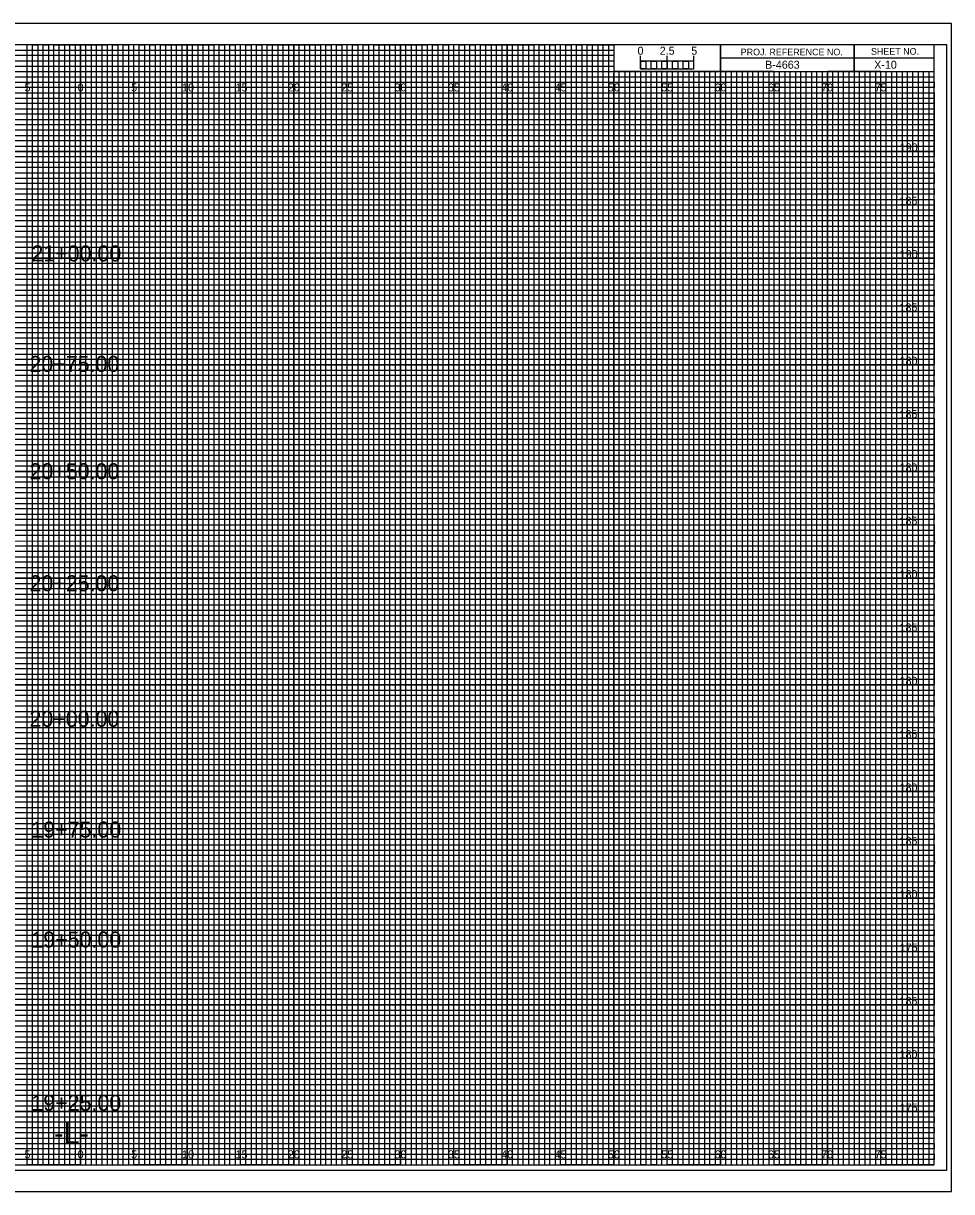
# Model space of a CAD drawing. Extents: x -7 to 162, y 878 to 987.
# Drawn here: x 74.6 to 161.7, y 877.5 to 987 of the extents above; entities that cross this region are included whole.
import ezdxf

# ---------------------------------------------------------------- set-up
doc = ezdxf.new("R2010")
doc.units = 0
for name, color, linetype in [('Prop XS Alignment Label', 7, 'Continuous'), ('Prop XS Bar Scale Labels', 7, 'Continuous'), ('Prop XS Elevation Labels', 7, 'Continuous'), ('Prop XS Offset Labels', 7, 'Continuous'), ('Prop XS Project Number', 7, 'Continuous'), ('Prop XS Sheet Number', 7, 'Continuous'), ('Prop XS Station Labels', 7, 'Continuous'), ('Sheet Cross Section CELL', 7, 'Continuous'), ('Sheet Cross Section Grid Major CELL', 7, 'Continuous'), ('Sheet Cross Section Grid Middle CELL', 7, 'Continuous'), ('Sheet Cross Section Grid Minor 1 CELL', 7, 'Continuous'), ('Sheet Cross Section Grid Minor 2 CELL', 7, 'Continuous'), ('Sheet Cross Section Scale CELL', 7, 'Continuous'), ('Sheet Cutting Line CELL', 7, 'Continuous'), ('Sheet DOT Grid CELL', 7, 'Continuous'), ('Sheet Plot Border Inside CELL', 7, 'Continuous'), ('Sheet Plot Border Outside CELL', 7, 'Continuous')]:
    doc.layers.add(name, color=color, linetype=linetype)

msp = doc.modelspace()

# ---------------------------------------------------------------- linework, layer by layer
at = {"layer": 'Sheet Cross Section CELL'}
for p, q in [((152.5, 985), (152.5, 982.5)), ((152.5, 982.5), (152.5, 985)), ((160, 983.75), (140, 983.75)), ((140, 983.75), (140, 982.5)), ((140, 982.5), (160, 982.5))]:
    msp.add_line(p, q, dxfattribs=at)
for points in [[(160, 985), (0, 985), (0, 880), (160, 880)], [(140, 985), (130, 985), (130, 982.51), (140, 982.51)], [(160, 985), (140, 985), (140, 982.5), (160, 982.5)]]:
    msp.add_lwpolyline(points, close=True, dxfattribs=at)
at = {"layer": 'Sheet Cross Section Grid Major CELL'}
for p, q in [((75, 985), (70, 985)), ((75, 880), (75, 985)), ((85, 985), (80, 985)), ((80, 985), (80, 880)), ((85, 880), (85, 985)), ((95, 985), (90, 985)), ((90, 985), (90, 880)), ((95, 880), (95, 985)), ((105, 985), (100, 985)), ((100, 985), (100, 880)), ((105, 880), (105, 985)), ((115, 985), (110, 985)), ((110, 985), (110, 880)), ((115, 880), (115, 985)), ((125, 985), (120, 985)), ((120, 985), (120, 880)), ((125, 880), (125, 985)), ((130, 985), (130, 880)), ((135, 880), (135, 982.5)), ((145, 982.5), (140, 982.5)), ((140, 982.5), (140, 880)), ((145, 880), (145, 982.5)), ((155, 982.5), (150, 982.5)), ((150, 982.5), (150, 880)), ((155, 880), (155, 982.5)), ((80, 880), (75, 880)), ((90, 880), (85, 880)), ((100, 880), (95, 880)), ((110, 880), (105, 880)), ((120, 880), (115, 880)), ((130, 880), (125, 880)), ((140, 880), (135, 880)), ((150, 880), (145, 880)), ((160, 880), (155, 880)), ((160, 880), (160, 880))]:
    msp.add_line(p, q, dxfattribs=at)
for points in [[(0, 980), (160, 980), (160, 975), (0, 975)], [(0, 970), (160, 970), (160, 965), (0, 965)], [(0, 960), (160, 960), (160, 955), (0, 955)], [(0, 950), (160, 950), (160, 945), (0, 945)], [(0, 940), (160, 940), (160, 935), (0, 935)], [(0, 930), (160, 930), (160, 925), (0, 925)], [(0, 920), (160, 920), (160, 915), (0, 915)], [(0, 910), (160, 910), (160, 905), (0, 905)], [(0, 900), (160, 900), (160, 895), (0, 895)], [(0, 890), (160, 890), (160, 885), (0, 885)]]:
    msp.add_lwpolyline(points, dxfattribs=at)
at = {"layer": 'Sheet Cross Section Grid Middle CELL'}
for points in [[(72.5, 880), (77.5, 880), (77.5, 985), (82.5, 985), (82.5, 880), (87.5, 880), (87.5, 985), (92.5, 985), (92.5, 880), (97.5, 880), (97.5, 985), (102.5, 985), (102.5, 880), (107.5, 880), (107.5, 985), (112.5, 985), (112.5, 880), (117.5, 880), (117.5, 985), (122.5, 985), (122.5, 880), (127.5, 880), (127.5, 985), (129.97, 985), (130, 985), (130, 982.5), (132.5, 982.5), (132.5, 880), (137.5, 880), (137.5, 982.5), (142.5, 982.5), (142.5, 880), (147.5, 880), (147.5, 982.5), (152.5, 982.5), (152.5, 880), (157.5, 880), (157.5, 982.5)], [(0, 982.5), (137.5, 982.5)], [(0, 972.5), (160, 972.5), (160, 977.5), (0, 977.5)], [(0, 962.5), (160, 962.5), (160, 967.5), (0, 967.5)], [(0, 952.5), (160, 952.5), (160, 957.5), (0, 957.5)], [(0, 942.5), (160, 942.5), (160, 947.5), (0, 947.5)], [(0, 932.5), (160, 932.5), (160, 937.5), (0, 937.5)], [(0, 922.5), (160, 922.5), (160, 927.5), (0, 927.5)], [(0, 912.5), (160, 912.5), (160, 917.5), (0, 917.5)], [(0, 902.5), (160, 902.5), (160, 907.5), (0, 907.5)], [(0, 892.5), (160, 892.5), (160, 897.5), (0, 897.5)], [(0, 882.5), (160, 882.5), (160, 887.5), (0, 887.5)]]:
    msp.add_lwpolyline(points, dxfattribs=at)
at = {"layer": 'Sheet Cross Section Grid Minor 1 CELL'}
for p, q in [((0, 984.5), (130, 984.5)), ((130, 984.5), (130, 983.99)), ((130, 983.99), (0, 983.99)), ((0, 983.5), (130, 983.5)), ((130, 983.5), (130, 982.95)), ((130, 982.95), (0, 982.95)), ((0, 982), (160, 982))]:
    msp.add_line(p, q, dxfattribs=at)
for points in [[(0, 981.5), (135, 981.5), (160, 981.5), (160, 981), (0, 981)], [(0, 980.5), (160, 980.5), (160, 979.5), (0, 979.5)], [(0, 979), (160, 979), (160, 978.5), (0, 978.49)], [(0, 978), (160, 978), (160, 977), (0, 977)], [(0, 976.5), (160, 976.5), (160, 976), (0, 976)], [(0, 975.5), (160, 975.5), (160, 974.5), (0, 974.5)], [(0, 974), (160, 974), (160, 973.5), (0, 973.5)], [(0, 973), (160, 973), (160, 972), (0, 972)], [(0, 971.5), (160, 971.5), (160, 971), (0, 971)], [(0, 970.5), (160, 970.5), (160, 969.5), (0, 969.5)], [(0, 969), (160, 969), (160, 968.5), (0, 968.5)], [(0, 968), (160, 968), (160, 966.98), (160, 966.5), (160, 966), (0, 966)], [(0, 967), (160, 967), (160, 966.5), (0, 966.5)], [(0, 965.5), (160, 965.5), (160, 964.5), (0, 964.51)], [(0, 964.51), (160, 964.5), (160, 964), (0, 964)], [(0, 963.5), (160, 963.5), (160, 963), (0, 963)], [(0, 962), (160, 962), (160, 961.5), (0, 961.5)], [(0, 961), (160, 961), (160, 960.5), (0, 960.5)], [(-0.04, 959.45), (160, 959.45), (160, 958.94), (-0.04, 958.94)], [(0, 958.5), (160, 958.5), (160, 958), (0, 958)], [(0, 957), (160, 957), (160, 956.5), (0, 956.5)], [(0, 956), (160, 956), (160, 955.5), (0, 955.5)], [(0, 954.5), (160, 954.5), (160, 954), (0, 954)], [(0, 953.5), (160, 953.5), (160, 953), (0, 953)], [(0, 952), (160, 952), (160, 951.5), (0, 951.5)], [(0, 951), (160, 951), (160, 950.5), (0, 950.5)], [(0, 949.5), (160, 949.5), (160, 948.99), (0, 949)], [(0, 948.5), (160, 948.5), (160, 948), (0, 948)], [(0, 947), (160, 947), (160, 946.5), (0, 946.5)], [(0, 946), (160, 946), (160, 945.5), (0, 945.5)], [(0, 944.5), (160, 944.5), (160, 944), (0, 944)], [(0, 943.5), (160, 943.5), (160, 943), (0, 943)], [(0, 942), (160, 942), (160, 941.5), (0, 941.5)], [(0, 941), (160, 941), (160, 940.5), (0, 940.5)], [(0, 939.5), (160, 939.5), (160, 939), (0, 939)], [(0, 938.5), (160.03, 938.46), (160, 938), (0, 938)], [(0, 937), (160, 937), (160, 936.5), (0, 936.5)], [(0, 936), (160, 936), (160, 935.5), (0, 935.5)], [(0, 934.5), (160, 934.5), (160, 934), (0, 934)], [(0, 933.5), (160, 933.5), (160, 933), (0, 933)], [(0, 932), (160, 932), (160, 931.5), (0, 931.5)], [(0, 931), (160, 931), (160, 930.5), (0, 930.5)], [(0, 929.5), (160, 929.5), (160, 929), (0, 929)], [(0, 928.5), (160, 928.5), (160, 928), (0, 928)], [(0, 927), (160, 927), (160, 926.5), (0, 926.5)], [(0, 926), (160, 926), (160, 925.5), (0, 925.5)], [(0, 924.5), (160, 924.5), (160, 924), (0, 924)], [(0, 923.5), (160, 923.5), (160, 923), (0, 923)], [(0, 922), (160, 922), (160, 921.5), (0, 921.5)], [(0, 921), (160, 921), (160, 920.5), (0, 920.5)], [(0, 919.5), (160, 919.5), (160, 918.99), (0, 919)], [(0, 918.5), (160, 918.5), (160, 918), (0, 918)], [(0, 917), (160, 917), (160, 916.5), (0, 916.5)], [(0, 916), (160, 916), (160, 915.5), (0, 915.5)], [(0, 914.5), (160, 914.5), (160, 914), (0, 914)], [(0, 913.5), (160, 913.5), (160, 913), (0, 913)], [(0, 912), (160, 912), (160, 911.5), (0, 911.5)], [(0, 911), (160, 911), (160, 910.5), (0, 910.5)], [(0, 909.5), (160, 909.5), (160, 909), (0, 909)], [(0, 908.5), (160.03, 908.46), (160, 908), (0, 908)], [(0, 907), (160, 907), (160, 906.5), (0, 906.5)], [(0, 906), (160, 906), (160, 905.5), (0, 905.5)], [(0, 904.5), (160, 904.5), (160, 904), (0, 904)], [(0, 903.5), (160, 903.5), (160, 903), (0, 903)], [(0, 902), (160, 902), (160, 901.5), (0, 901.5)], [(0, 901), (160, 901), (160, 900.5), (0, 900.5)], [(0, 899.5), (160, 899.5), (160, 899), (0, 899)], [(0, 898.5), (160, 898.5), (160, 898), (0, 898)], [(0, 897), (160, 897), (160, 896.5), (0, 896.5)], [(0, 896), (160, 896), (160, 895.5), (0, 895.5)], [(0, 894.5), (160, 894.5), (160, 894), (0, 894)], [(0, 893.5), (160, 893.5), (160, 893), (0, 893)], [(0, 892), (160, 892), (160, 891.5), (0, 891.5)], [(0, 891), (160, 891), (160, 890.5), (0, 890.5)], [(0, 889.5), (160, 889.5), (160, 889), (0, 889)], [(0, 888.5), (160, 888.5), (160, 888), (0, 888)], [(0, 887), (160, 887), (160, 886.5), (0, 886.5)], [(0, 886), (160, 886), (160, 885.5), (0, 885.5)], [(0, 884.5), (160, 884.5), (160, 884), (0, 884)], [(0, 883.5), (160, 883.5), (160, 883), (0, 883)], [(0, 882), (160, 882), (160, 881.5), (0, 881.5)], [(0, 881), (160, 881), (160, 880.5), (0, 880.5)]]:
    msp.add_lwpolyline(points, dxfattribs=at)
at = {"layer": 'Sheet Cross Section Grid Minor 2 CELL'}
for p, q in [((133.5, 982.5), (133, 982.5)), ((133, 982.5), (133, 880)), ((133.5, 880), (133.5, 982.5)), ((134.5, 982.5), (134, 982.5)), ((134, 982.5), (134, 880)), ((134.5, 880), (134.5, 982.5)), ((133, 880), (132.5, 880)), ((134, 880), (133.5, 880))]:
    msp.add_line(p, q, dxfattribs=at)
for points in [[(75, 880), (75.5, 880), (75.5, 985), (76, 985), (76, 880)], [(76, 880), (76.5, 880), (76.5, 985), (77, 985), (77, 880)], [(77.5, 880), (78, 880), (78, 985), (78.5, 985), (78.5, 880)], [(78.5, 880), (79, 880), (79, 985), (79.5, 985), (79.5, 880)], [(80, 880), (80.5, 880), (80.5, 985), (81, 985), (81, 880)], [(81, 880), (81.5, 880), (81.5, 985), (82, 985), (82, 880)], [(82.5, 880), (83, 880), (83, 985), (83.5, 985), (83.5, 880)], [(83.5, 880), (84, 880), (84, 985), (84.5, 985), (84.5, 880)], [(85, 880), (85.5, 880), (85.5, 985), (86, 985), (86, 880)], [(86, 880), (86.5, 880), (86.5, 985), (87, 985), (87, 880)], [(87.5, 880), (88, 880), (88, 985), (88.5, 985), (88.5, 880)], [(88.5, 880), (89, 880), (89, 985), (89.5, 985), (89.5, 880)], [(90, 880), (90.5, 880), (90.5, 985), (91, 985), (91, 880)], [(91, 880), (91.5, 880), (91.5, 985), (92, 985), (92, 880)], [(92.5, 880), (93, 880), (93, 985), (93.5, 985), (93.5, 880)], [(93.5, 880), (94, 880), (94, 985), (94.5, 985), (94.5, 880)], [(95, 880), (95.5, 880), (95.5, 985), (96, 985), (96, 880)], [(96, 880), (96.5, 880), (96.5, 985), (97, 985), (97, 880)], [(97.5, 880), (98, 880), (98, 985), (98.5, 985), (98.5, 880)], [(98.5, 880), (99, 880), (99, 985), (99.5, 985), (99.5, 880)], [(100, 880), (100.5, 880), (100.5, 985), (101, 985), (101, 880)], [(101, 880), (101.5, 880), (101.5, 985), (102, 985), (102, 880)], [(102.5, 880), (103, 880), (103, 985), (103.5, 985), (103.5, 880)], [(103.5, 880), (104, 880), (104, 985), (104.5, 985), (104.5, 880)], [(105, 880), (105.5, 880), (105.5, 985), (106, 985), (106, 880)], [(106, 880), (106.5, 880), (106.5, 985), (107, 985), (107, 880)], [(107.5, 880), (108, 880), (108, 985), (108.5, 985), (108.5, 880)], [(108.5, 880), (109, 880), (109, 985), (109.5, 985), (109.5, 880)], [(110, 880), (110.5, 880), (110.5, 985), (111, 985), (111, 880)], [(111, 880), (111.5, 880), (111.5, 985), (112, 985), (112, 880)], [(112.5, 880), (113, 880), (113, 985), (113.5, 985), (113.5, 880)], [(113.5, 880), (114, 880), (114, 985), (114.5, 985), (114.5, 880)], [(115, 880), (115.5, 880), (115.5, 985), (116, 985), (116, 880)], [(116, 880), (116.5, 880), (116.5, 985), (117, 985), (117, 880)], [(117.5, 880), (118, 880), (118, 985), (118.5, 985), (118.5, 880)], [(118.5, 880), (119, 880), (119, 985), (119.5, 985), (119.5, 880)], [(120, 880), (120.5, 880), (120.5, 985), (121, 985), (121, 880)], [(121, 880), (121.5, 880), (121.5, 985), (122, 985), (122, 880)], [(122.5, 880), (123, 880), (123, 985), (123.5, 985), (123.5, 880)], [(123.5, 880), (124, 880), (124, 985), (124.5, 985), (124.5, 880)], [(125, 880), (125.5, 880), (125.5, 985), (126, 985), (126, 880)], [(126, 880), (126.5, 880), (126.5, 985), (127, 985), (127, 880)], [(127.5, 880), (128, 880), (128, 985), (128.5, 985), (128.5, 880)], [(128.5, 880), (129, 880), (129, 985), (129.5, 985), (129.5, 880)], [(130, 880), (130.5, 880), (130.5, 982.5), (131.01, 982.5), (131.01, 880)], [(131, 880), (131.5, 880), (131.5, 982.5), (132, 982.5), (132, 880)], [(135, 880), (135.49, 880), (135.49, 982.5), (136, 982.5), (136, 880)], [(136, 880), (136.5, 880), (136.5, 982.5), (137.03, 982.5), (137.03, 880)], [(137.5, 880), (138, 880), (138, 982.5), (138.5, 982.5), (138.5, 880)], [(138.5, 880), (139, 880), (139, 982.5), (139.5, 982.5), (139.5, 880)], [(140, 880), (140.5, 880), (140.5, 982.5), (141, 982.5), (141, 880)], [(141, 880), (141.5, 880), (141.5, 982.5), (142, 982.5), (142, 880)], [(142.5, 880), (143, 880), (143, 982.5), (143.5, 982.5), (143.5, 880)], [(143.5, 880), (144, 880), (144, 982.5), (144.5, 982.5), (144.5, 880)], [(145, 880), (145.5, 880), (145.5, 982.5), (146, 982.5), (146, 880)], [(146, 880), (146.5, 880), (146.5, 982.5), (147, 982.5), (147, 880)], [(147.5, 880), (148, 880), (148, 982.5), (148.5, 982.5), (148.5, 880)], [(148.5, 880), (149, 880), (149, 982.5), (149.5, 982.5), (149.5, 880)], [(150, 880), (150.5, 880), (150.5, 982.5), (151, 982.5), (151, 880)], [(151, 880), (151.5, 880), (151.5, 982.5), (152, 982.5), (152, 880)], [(152.5, 880), (153, 880), (153, 982.5), (153.5, 982.5), (153.5, 880)], [(153.5, 880), (154, 880), (154, 982.5), (154.5, 982.5), (154.5, 880)], [(155, 880), (155.5, 880), (155.5, 982.5), (156, 982.5), (156, 880)], [(156, 880), (156.5, 880), (156.5, 982.5), (157, 982.5), (157, 880)], [(157.5, 880), (158, 880), (158, 982.5), (158.5, 982.5), (158.5, 880)], [(158.5, 880), (159, 880), (159, 982.5), (159.5, 982.5), (159.5, 880)]]:
    msp.add_lwpolyline(points, dxfattribs=at)
at = {"layer": 'Sheet Cross Section Scale CELL'}
for p, q in [((132.5, 982.75), (132.5, 983.95)), ((132.5, 983.45), (132.5, 983.95)), ((135, 982.75), (135, 983.95)), ((137.5, 982.75), (137.5, 983.95)), ((137.5, 983.45), (137.5, 983.95))]:
    msp.add_line(p, q, dxfattribs=at)
for points in [[(137.5, 983.45), (132.5, 983.45), (132.5, 982.75), (137.5, 982.75)], [(132.5, 983.45), (133, 983.45), (133, 982.75), (132.5, 982.75)], [(133.5, 983.45), (134, 983.45), (134, 982.75), (133.5, 982.75)], [(134.5, 983.45), (135, 983.45), (135, 982.75), (134.5, 982.75)], [(135.5, 983.45), (136, 983.45), (136, 982.75), (135.5, 982.75)], [(136.5, 983.45), (137, 983.45), (137, 982.75), (136.5, 982.75)]]:
    msp.add_lwpolyline(points, close=True, dxfattribs=at)
at = {"layer": 'Sheet Cutting Line CELL'}
for p, q in [((161.65, 987), (-6.7, 987)), ((-6.7, 877.5), (161.65, 877.5))]:
    msp.add_line(p, q, dxfattribs=at)
at = {"layer": 'Sheet DOT Grid CELL'}
for p, q in [((75, 880), (75, 985)), ((80, 880), (80, 985)), ((85, 880), (85, 985)), ((90, 880), (90, 985)), ((95, 880), (95, 985)), ((100, 880), (100, 985)), ((105, 880), (105, 985)), ((110, 880), (110, 985)), ((115, 880), (115, 985)), ((120, 880), (120, 985)), ((125, 880), (125, 985)), ((130, 880), (130, 982.34)), ((135, 880), (135, 982.34)), ((140, 880), (140, 982.34)), ((145, 880), (145, 982.34)), ((150, 880), (150, 982.34)), ((155, 880), (155, 982.34)), ((0, 980), (160, 980)), ((0, 975), (160, 975)), ((0, 970), (160, 970)), ((0, 965), (160, 965)), ((0, 960), (160, 960)), ((0, 955), (160, 955)), ((0, 950), (160, 950)), ((0, 945), (160, 945)), ((0, 940), (160, 940)), ((0, 935), (160, 935)), ((0, 930), (160, 930)), ((0, 925), (160, 925)), ((0, 920), (160, 920)), ((0, 915), (160, 915)), ((0, 910), (160, 910)), ((0, 905), (160, 905)), ((0, 900), (160, 900)), ((0, 895), (160, 895)), ((0, 890), (160, 890)), ((0, 885), (160, 885))]:
    msp.add_line(p, q, dxfattribs=at)
at = {"layer": 'Sheet Plot Border Inside CELL'}
msp.add_lwpolyline([(-5.4, 879.5), (161.2, 879.5), (161.2, 985), (-5.4, 985)], close=True, dxfattribs=at)
at = {"layer": 'Sheet Plot Border Outside CELL'}
msp.add_lwpolyline([(-6.7, 877.5), (161.65, 877.5), (161.65, 987), (-6.7, 987)], close=True, dxfattribs=at)

# ---------------------------------------------------------------- texts
at = {"layer": 'Prop XS Alignment Label'}
msp.add_text('-L-', height=2, dxfattribs=at).set_placement((77.53, 882))
at = {"layer": 'Prop XS Bar Scale Labels'}
for s, p in [('2.5', (134.29, 984.06)), ('5', (137.24, 984.06))]:
    msp.add_text(s, height=0.75, dxfattribs=at).set_placement(p)
at = {"layer": 'Prop XS Elevation Labels'}
for s, p in [('190', (156.79, 975)), ('185', (156.76, 970)), ('190', (156.79, 965)), ('185', (156.76, 960)), ('180', (156.77, 955)), ('185', (156.76, 950)), ('180', (156.77, 945)), ('185', (156.76, 940)), ('180', (156.77, 935)), ('185', (156.76, 930)), ('180', (156.77, 925)), ('185', (156.76, 920)), ('180', (156.77, 915)), ('185', (156.76, 910)), ('180', (156.77, 905)), ('175', (156.79, 900)), ('185', (156.76, 895)), ('180', (156.77, 890)), ('175', (156.79, 885))]:
    msp.add_text(s, height=0.75, dxfattribs=at).set_placement(p)
at = {"layer": 'Prop XS Offset Labels'}
for s, p in [('5', (74.74, 980.62)), ('0', (79.73, 980.62)), ('0', (79.73, 980.62)), ('5', (84.74, 980.62)), ('10', (89.52, 980.62)), ('15', (94.53, 980.62)), ('20', (99.43, 980.62)), ('25', (104.44, 980.62)), ('30', (109.43, 980.62)), ('35', (114.44, 980.62)), ('40', (119.43, 980.62)), ('45', (124.44, 980.62)), ('50', (129.43, 980.62)), ('55', (134.44, 980.62)), ('60', (139.43, 980.62)), ('65', (144.44, 980.62)), ('70', (149.43, 980.62)), ('75', (154.44, 980.62)), ('5', (74.74, 880.62)), ('0', (79.73, 880.62)), ('0', (79.73, 880.62)), ('5', (84.74, 880.62)), ('10', (89.52, 880.62)), ('15', (94.53, 880.62)), ('20', (99.43, 880.62)), ('25', (104.44, 880.62)), ('30', (109.43, 880.62)), ('35', (114.44, 880.62)), ('40', (119.43, 880.62)), ('45', (124.44, 880.62)), ('50', (129.43, 880.62)), ('55', (134.44, 880.62)), ('60', (139.43, 880.62)), ('65', (144.44, 880.62)), ('70', (149.43, 880.62)), ('75', (154.44, 880.62))]:
    msp.add_text(s, height=0.75, dxfattribs=at).set_placement(p)
at = {"layer": 'Prop XS Project Number'}
msp.add_text('B-4663', height=0.75, dxfattribs=at).set_placement((144.17, 982.75))
at = {"layer": 'Prop XS Sheet Number'}
msp.add_text('X-10', height=0.75, dxfattribs=at).set_placement((154.39, 982.75))
at = {"layer": 'Prop XS Station Labels'}
for s, p in [('21+00.00', (75.39, 964.69)), ('20+75.00', (75.21, 954.33)), ('20+50.00', (75.21, 944.27)), ('20+25.00', (75.21, 933.77)), ('20+00.00', (75.21, 921.07)), ('19+75.00', (75.39, 910.69)), ('19+50.00', (75.39, 900.38)), ('19+25.00', (75.39, 885.08))]:
    msp.add_text(s, height=1.5, dxfattribs=at).set_placement(p)
at = {"layer": 'Sheet Cross Section CELL'}
for s, p in [('PROJ. REFERENCE NO.', (141.88, 984)), ('SHEET NO.', (154.09, 984.06))]:
    msp.add_text(s, height=0.625, dxfattribs=at).set_placement(p)
at = {"layer": 'Sheet Cross Section Scale CELL'}
msp.add_text('0', height=0.75, dxfattribs=at).set_placement((132.21, 984.06))

doc.saveas('drawing.dxf')
